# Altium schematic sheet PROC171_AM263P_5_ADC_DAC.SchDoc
size 431 x 279 mm; Date: Not shown in title block; ApprovedBy: Not shown in title block; CheckedBy: Not shown in title block; Author: Not shown in title block; CompanyName: Not shown in title block; Engineer: Not shown in title block; Organization: Not shown in title block; Address1: Not shown in title block; Address2: Not shown in title block; Address3: Not shown in title block; Address4: Not shown in title block; DocumentNumber: 10; Revision: Use project parameter SCH_Rev; SheetNumber: 10; SheetTotal: 27; PageSetup: Record=PageOptions¦CenterHorizontal=True¦CenterVertical=True¦PrintScale=1.00¦XCorrection=1.00¦YCorrection=1.00¦PrintKind=0¦BorderSize=5000000¦LeftOffset=0¦BottomOffset=0¦Orientation=2¦PaperLength=1000¦PaperWidth=1000¦Scale=100¦PaperSource=15¦PrintQuality=600¦MediaType=1¦DitherType=10¦PaperKind=Letter¦PrintScaleMode=1
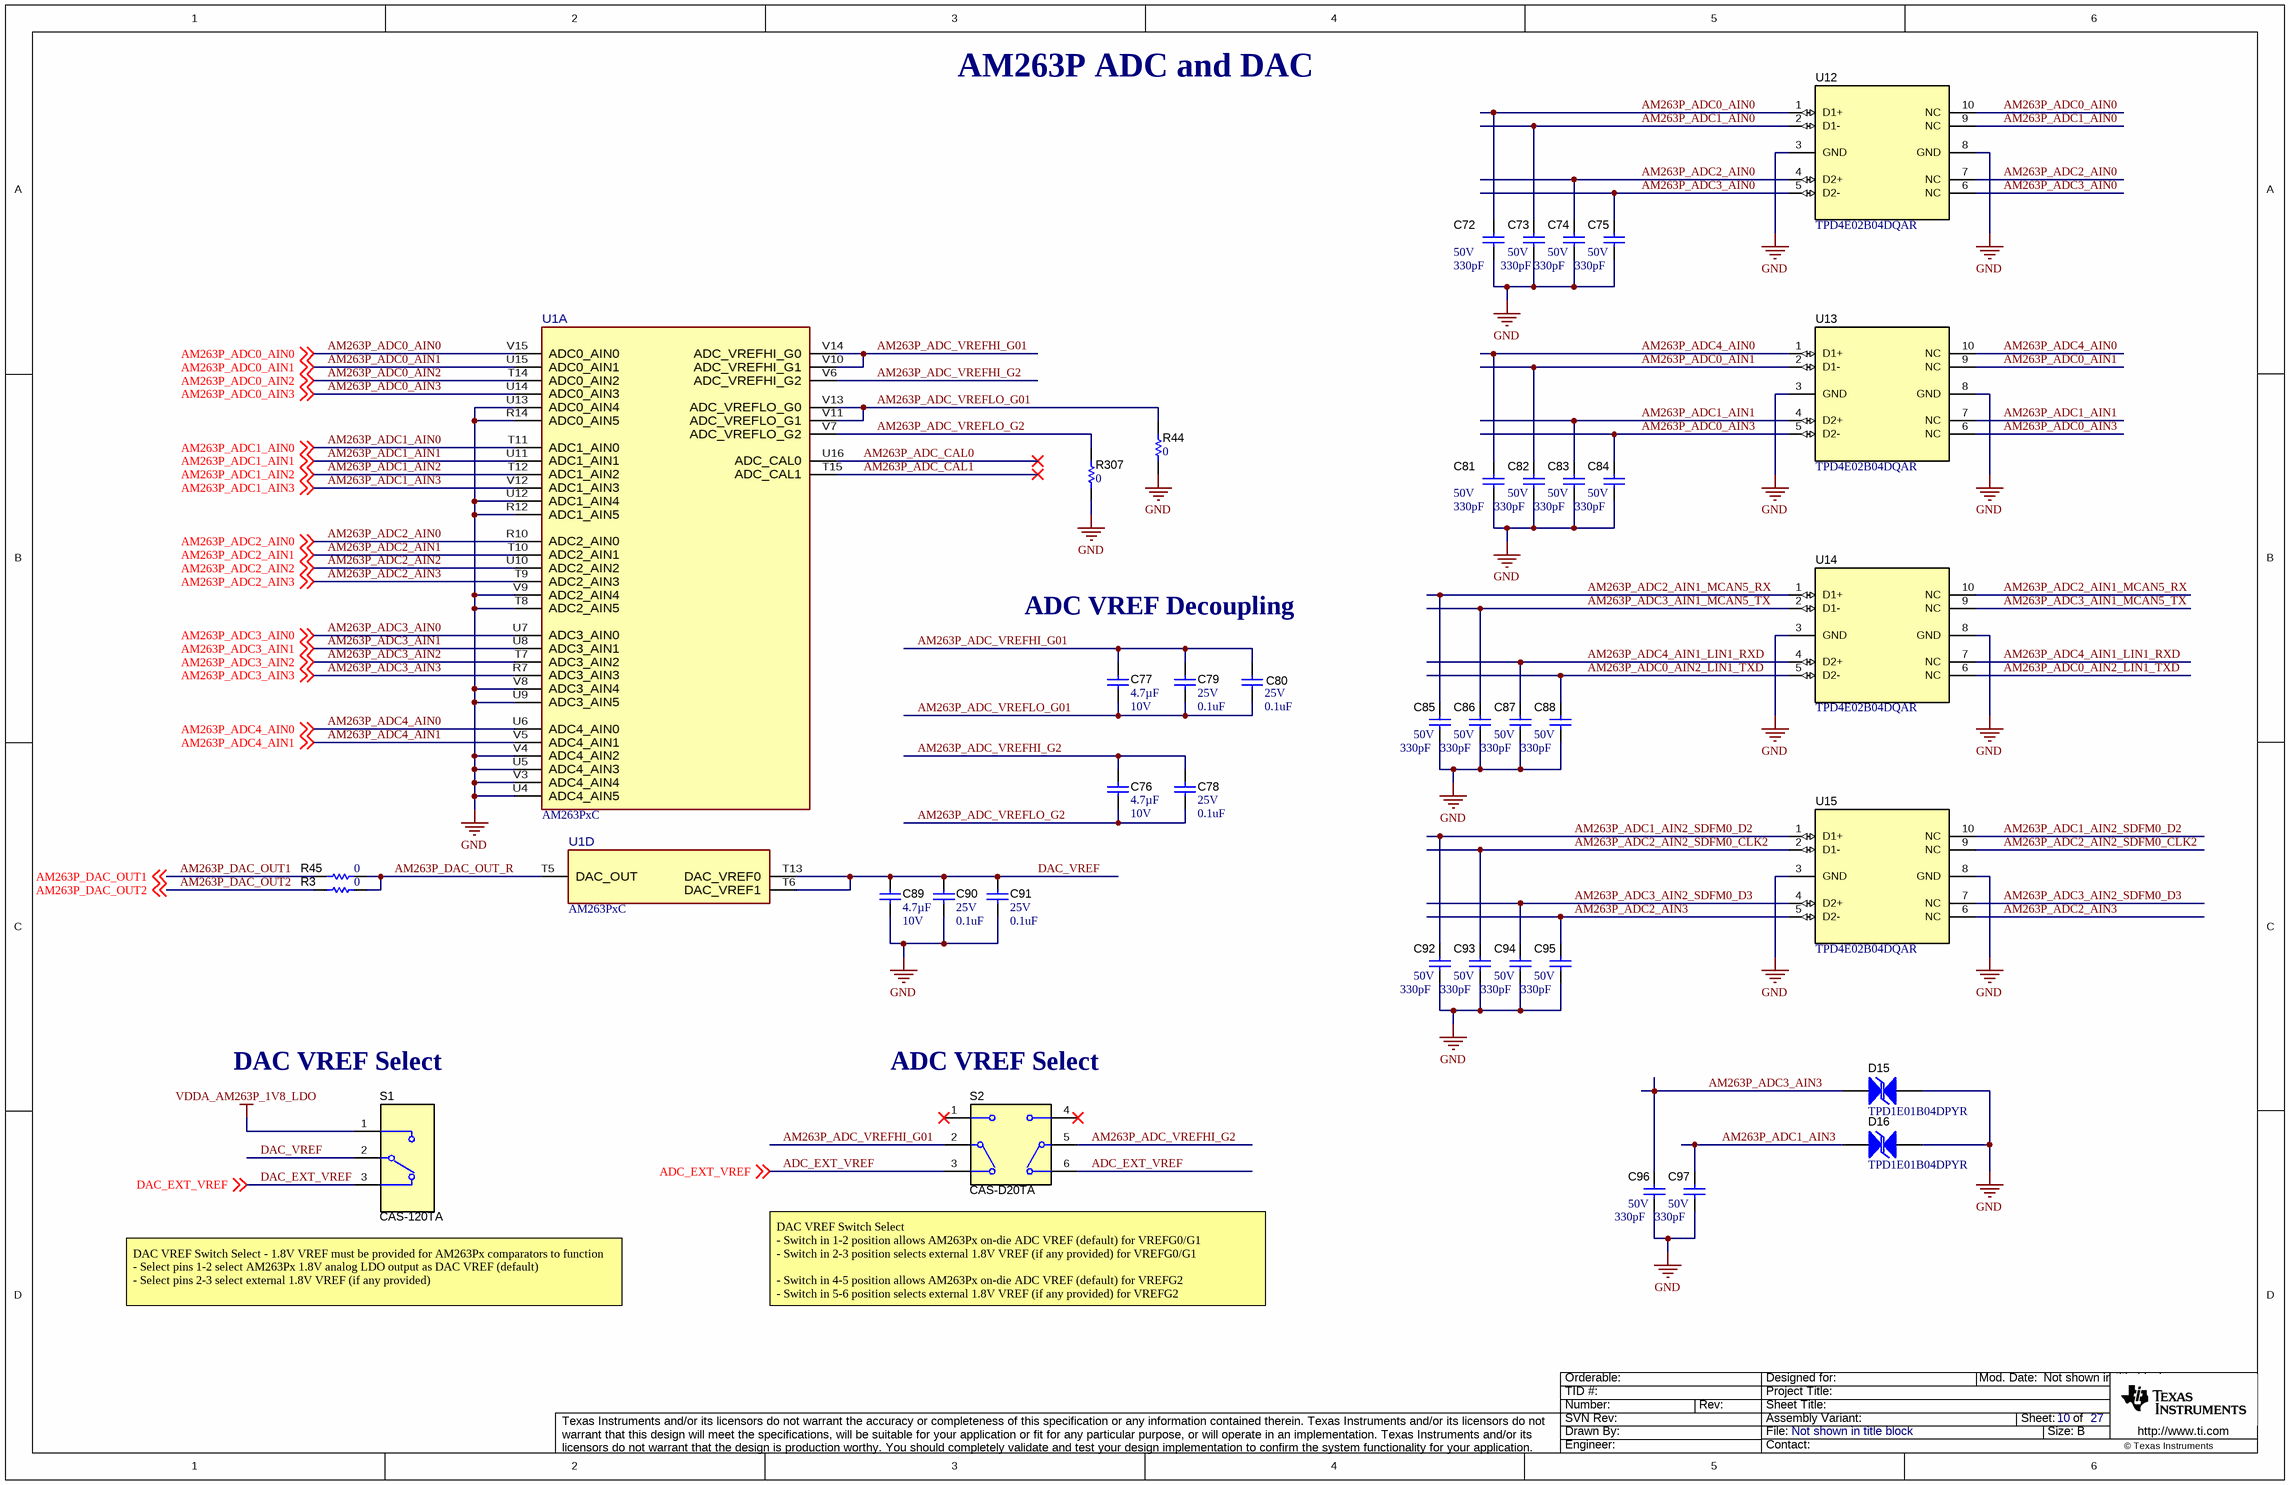
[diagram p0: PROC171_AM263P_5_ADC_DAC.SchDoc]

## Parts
C72  VDC_V: 50V  ValueDisplayed: 330pF  [0402]  (hidden comment: GRM1555C1H331JA01D)
C73  VDC_V: 50V  ValueDisplayed: 330pF  [0402]  (hidden comment: GRM1555C1H331JA01D)
C74  VDC_V: 50V  ValueDisplayed: 330pF  [0402]  (hidden comment: GRM1555C1H331JA01D)
C75  VDC_V: 50V  ValueDisplayed: 330pF  [0402]  (hidden comment: GRM1555C1H331JA01D)
C76  Cap_F: 4.7µF  VDC_V: 10V  [0603]  (hidden comment: GRM188Z71A475ME15D)
C77  Cap_F: 4.7µF  VDC_V: 10V  [0603]  (hidden comment: GRM188Z71A475ME15D)
C78  VDC_V: 25V  ValueDisplayed: 0.1uF  [0402]  (hidden comment: GRM155R71E104KE14D)
C79  VDC_V: 25V  ValueDisplayed: 0.1uF  [0402]  (hidden comment: GRM155R71E104KE14D)
C80  VDC_V: 25V  ValueDisplayed: 0.1uF  [0402]  (hidden comment: GRM155R71E104KE14D)
C81  VDC_V: 50V  ValueDisplayed: 330pF  [0402]  (hidden comment: GRM1555C1H331JA01D)
C82  VDC_V: 50V  ValueDisplayed: 330pF  [0402]  (hidden comment: GRM1555C1H331JA01D)
C83  VDC_V: 50V  ValueDisplayed: 330pF  [0402]  (hidden comment: GRM1555C1H331JA01D)
C84  VDC_V: 50V  ValueDisplayed: 330pF  [0402]  (hidden comment: GRM1555C1H331JA01D)
C85  VDC_V: 50V  ValueDisplayed: 330pF  [0402]  (hidden comment: GRM1555C1H331JA01D)
C86  VDC_V: 50V  ValueDisplayed: 330pF  [0402]  (hidden comment: GRM1555C1H331JA01D)
C87  VDC_V: 50V  ValueDisplayed: 330pF  [0402]  (hidden comment: GRM1555C1H331JA01D)
C88  VDC_V: 50V  ValueDisplayed: 330pF  [0402]  (hidden comment: GRM1555C1H331JA01D)
C89  Cap_F: 4.7µF  VDC_V: 10V  [0603]  (hidden comment: GRM188Z71A475ME15D)
C90  VDC_V: 25V  ValueDisplayed: 0.1uF  [0402]  (hidden comment: GRM155R71E104KE14D)
C91  VDC_V: 25V  ValueDisplayed: 0.1uF  [0402]  (hidden comment: GRM155R71E104KE14D)
C92  VDC_V: 50V  ValueDisplayed: 330pF  [0402]  (hidden comment: GRM1555C1H331JA01D)
C93  VDC_V: 50V  ValueDisplayed: 330pF  [0402]  (hidden comment: GRM1555C1H331JA01D)
C94  VDC_V: 50V  ValueDisplayed: 330pF  [0402]  (hidden comment: GRM1555C1H331JA01D)
C95  VDC_V: 50V  ValueDisplayed: 330pF  [0402]  (hidden comment: GRM1555C1H331JA01D)
C96  VDC_V: 50V  ValueDisplayed: 330pF  [0402]  (hidden comment: GRM1555C1H331JA01D)
C97  VDC_V: 50V  ValueDisplayed: 330pF  [0402]  (hidden comment: GRM1555C1H331JA01D)
D15  TPD1E01B04DPYR  [DPY0002A]
D16  TPD1E01B04DPYR  [DPY0002A]
R3  value 0  [0402L]  (hidden comment: ERJ-2GE0R00X)
R44  value 0  [0402L]  (hidden comment: ERJ-2GE0R00X)
R45  value 0  [0402L]  (hidden comment: ERJ-2GE0R00X)
R307  value 0  [0402L]  (hidden comment: ERJ-2GE0R00X)
S1  CAS-120TA  [SW_CAS-120TA]
S2  CAS-D20TA  [SW_CAS-D20TA]
U1  AM263PxC  [ZCZ0324A-MFG]  (parts A,D of 13)
U12  TPD4E02B04DQAR  [DQA0010A]
U13  TPD4E02B04DQAR  [DQA0010A]
U14  TPD4E02B04DQAR  [DQA0010A]
U15  TPD4E02B04DQAR  [DQA0010A]

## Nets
GND: C72.2 C73.2 C74.2 C75.2 C81.2 C82.2 C83.2 C84.2 C85.2 C86.2 C87.2 C88.2 C89.2 C90.2 C91.2 C92.2 C93.2 C94.2 C95.2 C96.2 C97.2 D15.1 D16.2 R44.1 R307.1 U1.R12(ADC1_AIN5) U1.R14(ADC0_AIN5) U1.T8(ADC2_AIN5) U1.U4(ADC4_AIN5) U1.U5(ADC4_AIN3) U1.U9(ADC3_AIN5) U1.U12(ADC1_AIN4) U1.U13(ADC0_AIN4) U1.V3(ADC4_AIN4) U1.V4(ADC4_AIN2) U1.V8(ADC3_AIN4) U1.V9(ADC2_AIN4) U12.3(GND) U12.8(GND) U13.3(GND) U13.8(GND) U14.3(GND) U14.8(GND) U15.3(GND) U15.8(GND)
VDDA_AM263P_1V8_LDO: S1.1
ADC_EXT_VREF: S2.3 S2.6 ; off-sheet ADC_EXT_VREF
AM263P_ADC0_AIN0: C72.1 U1.V15(ADC0_AIN0) U12.1(D1+) U12.10(NC) ; off-sheet AM263P_ADC0_AIN0
AM263P_ADC0_AIN1: C82.1 U1.U15(ADC0_AIN1) U13.2(D1-) U13.9(NC) ; off-sheet AM263P_ADC0_AIN1
AM263P_ADC0_AIN2: U1.T14(ADC0_AIN2) ; off-sheet AM263P_ADC0_AIN2
AM263P_ADC0_AIN2_LIN1_TXD: C88.1 U14.5(D2-) U14.6(NC)
AM263P_ADC0_AIN3: C84.1 U1.U14(ADC0_AIN3) U13.5(D2-) U13.6(NC) ; off-sheet AM263P_ADC0_AIN3
AM263P_ADC1_AIN0: C73.1 U1.T11(ADC1_AIN0) U12.2(D1-) U12.9(NC) ; off-sheet AM263P_ADC1_AIN0
AM263P_ADC1_AIN1: C83.1 U1.U11(ADC1_AIN1) U13.4(D2+) U13.7(NC) ; off-sheet AM263P_ADC1_AIN1
AM263P_ADC1_AIN2: U1.T12(ADC1_AIN2) ; off-sheet AM263P_ADC1_AIN2
AM263P_ADC1_AIN2_SDFM0_D2: C92.1 U15.1(D1+) U15.10(NC)
AM263P_ADC1_AIN3: C97.1 D16.1 U1.V12(ADC1_AIN3) ; off-sheet AM263P_ADC1_AIN3
AM263P_ADC2_AIN0: C74.1 U1.R10(ADC2_AIN0) U12.4(D2+) U12.7(NC) ; off-sheet AM263P_ADC2_AIN0
AM263P_ADC2_AIN1: U1.T10(ADC2_AIN1) ; off-sheet AM263P_ADC2_AIN1
AM263P_ADC2_AIN1_MCAN5_RX: C85.1 U14.1(D1+) U14.10(NC)
AM263P_ADC2_AIN2: U1.U10(ADC2_AIN2) ; off-sheet AM263P_ADC2_AIN2
AM263P_ADC2_AIN2_SDFM0_CLK2: C93.1 U15.2(D1-) U15.9(NC)
AM263P_ADC2_AIN3: C95.1 U1.T9(ADC2_AIN3) U15.5(D2-) U15.6(NC) ; off-sheet AM263P_ADC2_AIN3
AM263P_ADC3_AIN0: C75.1 U1.U7(ADC3_AIN0) U12.5(D2-) U12.6(NC) ; off-sheet AM263P_ADC3_AIN0
AM263P_ADC3_AIN1: U1.U8(ADC3_AIN1) ; off-sheet AM263P_ADC3_AIN1
AM263P_ADC3_AIN1_MCAN5_TX: C86.1 U14.2(D1-) U14.9(NC)
AM263P_ADC3_AIN2: U1.T7(ADC3_AIN2) ; off-sheet AM263P_ADC3_AIN2
AM263P_ADC3_AIN2_SDFM0_D3: C94.1 U15.4(D2+) U15.7(NC)
AM263P_ADC3_AIN3: C96.1 D15.2 U1.R7(ADC3_AIN3) ; off-sheet AM263P_ADC3_AIN3
AM263P_ADC4_AIN0: C81.1 U1.U6(ADC4_AIN0) U13.1(D1+) U13.10(NC) ; off-sheet AM263P_ADC4_AIN0
AM263P_ADC4_AIN1: U1.V5(ADC4_AIN1) ; off-sheet AM263P_ADC4_AIN1
AM263P_ADC4_AIN1_LIN1_RXD: C87.1 U14.4(D2+) U14.7(NC)
AM263P_ADC_CAL0: U1.U16(ADC_CAL0)
AM263P_ADC_CAL1: U1.T15(ADC_CAL1)
AM263P_ADC_VREFHI_G01: C77.1 C79.1 C80.1 S2.2(C) U1.V10(ADC_VREFHI_G1) U1.V14(ADC_VREFHI_G0)
AM263P_ADC_VREFHI_G2: C76.1 C78.1 S2.5(C) U1.V6(ADC_VREFHI_G2)
AM263P_ADC_VREFLO_G01: C77.2 C79.2 C80.2 R44.2 U1.V11(ADC_VREFLO_G1) U1.V13(ADC_VREFLO_G0)
AM263P_ADC_VREFLO_G2: C76.2 C78.2 R307.2 U1.V7(ADC_VREFLO_G2)
AM263P_DAC_OUT1: R45.1 ; off-sheet AM263P_DAC_OUT1
AM263P_DAC_OUT2: R3.1 ; off-sheet AM263P_DAC_OUT2
AM263P_DAC_OUT_R: R3.2 R45.2 U1.T5(DAC_OUT)
DAC_EXT_VREF: S1.3 ; off-sheet DAC_EXT_VREF
DAC_VREF: C89.1 C90.1 C91.1 S1.2 U1.T6(DAC_VREF1) U1.T13(DAC_VREF0)

Not connected (* = marked no-connect by the designer): S2 1* 4*

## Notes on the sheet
- AM263P ADC and DAC
- ADC VREF Decoupling
- DAC VREF Select
- (near S2) ADC VREF Select
- DAC VREF Switch Select - 1.8V VREF must be provided for AM263Px comparators to function
  - Select pins 1-2 select AM263Px 1.8V analog LDO output as DAC VREF (default)
  - Select pins 2-3 select external 1.8V VREF (if any provided)
- (near S2) DAC VREF Switch Select
  - Switch in 1-2 position allows AM263Px on-die ADC VREF (default) for VREFG0/G1
  - Switch in 2-3 position selects external 1.8V VREF (if any provided) for VREFG0/G1
  - Switch in 4-5 position allows AM263Px on-die ADC VREF (default) for VREFG2
  - Switch in 5-6 position selects external 1.8V VREF (if any provided) for VREFG2

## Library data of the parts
C72-C75 C81-C88 C92-C97 = CMP-0006456-2: CAP, CERM, 330 pF, 50 V, +/- 5%, C0G/NP0, 0402; Manufacturer: MuRata; TaMin_C: -55°C; Polarized: N; SizeAreaWB_mm2: 3; U/M: EA; Value: 330pF; TaMax_C: 125°C; SizeZ_mm: 0.6; SizeX_mm: 1; SizeY_mm: 0.5; AEC Category: Q200; Value1: Unknown
C76 C77 C89 = CMP-0007498-4: CAP, CERM, 4.7 uF, 10 V, +/- 20%, X7R, 0603; Manufacturer: MuRata; TaMin_C: -55°C; Polarized: N; SizeAreaWB_mm2: 4.68; Value1: Unknown; U/M: EA; Value: 4.7uF; TaMax_C: 125°C; SizeZ_mm: 1; SizeX_mm: 1.6; SizeY_mm: 0.8; SizeArea_mm2: 1.28; AEC Category: Q200
C78-C80 C90 C91 = CMP-0006659-2: CAP, CERM, 0.1 uF, 25 V, +/- 10%, X7R, 0402; Manufacturer: MuRata; TaMin_C: -55°C; Polarized: N; SizeAreaWB_mm2: 3; Value1: Unknown; U/M: EA; Value: 0.1uF; TaMax_C: 125°C; SizeZ_mm: 0.6; SizeX_mm: 1; SizeY_mm: 0.5; Cap_F: 100nF; AEC Category: Q200
D15 D16 = CMP-0073602-3: 1-Channel ESD Protection Diode for USB Type-C and Thunderbolt 3, DPY0002A (X1SON-2); Alternate Manufacturer: Texas Instruments; Alternate PartNumber: TPD1E01B04DPYT; AEC Category: Q200; SizeArea_mm2: 0.6; CompType: IC; SizeAreaWB_mm2: 3.2; SizeZ_mm: 0.45; Rating: Catalog; SizeX_mm: 1.0
R3 R44 R45 R307 = CMP-0026992-3: RES, 0, 5%, 0.1 W, AEC-Q200 Grade 0, 0402; Manufacturer: Panasonic; Power_W: 100mW; TempCo: 600 ppm/C; Value_Code: 0000; EIA_Code: E24; SizeX_mm: 1; SizeY_mm: 0.5; SizeZ_mm: 0.6; Value2: 0.1W; AEC Qualified: Y; VDC_V: 50V; AEC Category: Q200; SizeAreaWB_mm2: 3
S1 = CMP-0002139-2: Switch, Slide, SPDT  100mA, SMT; Manufacturer: Copal Electronics; CurrentRating_mA: 100A; SwitchFunction: On-On; VDC_V: 6V; PositionCount: 1
S2 = CMP-0002233-1: Switch, Dual SPDT,  2 Pos, 0.1A, 6VDC, SMD; Manufacturer: Copal Electronics; CurrentRating_mA: 100A; SwitchFunction: On-On; VDC_V: 6V; PositionCount: 2
U1 = CMP-0001698-2: Sitara™ Microcontroller; Manufacturer: Texas Instruments; SizeZ_mm: 1.4mm; Core Architecture: ARM Cortex-R5F; Data Bus Width: 32bits; Frequency_Fixed: 200MHz; Interface: I2C,SPI,UART,CAN,LIN,Ethernet,Other; Max Supply Voltage: 3.465V; Memory Size: 2MBytes; Memory Type: RAM; Min Supply Voltage: 1.14V; Number Of Cores: 1; Number Of I/Os: 140; Number Of I2C Channels: 4; Number Of Spi Channels: 5; Number Of Uart Channels: 6; Standoff Height: 0.35mm; AEC Category: Q200; CompType: IC
U12-U15 = CMP-0073612-3: 4-Channel ESD Protection Diode for USB Type-C and HDMI 2.0, DQA0010A (USON-10); Alternate Manufacturer: Texas Instruments; Green_Lifecycle: Active; SizeAreaWB_mm2: 7.0; Green_REACh: Passed; SizeZ_mm: 0.55; SizeX_mm: 1.0; SizeY_mm: 2.5; CompType: IC; AEC Category: Q200; AEC Qualified: Y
